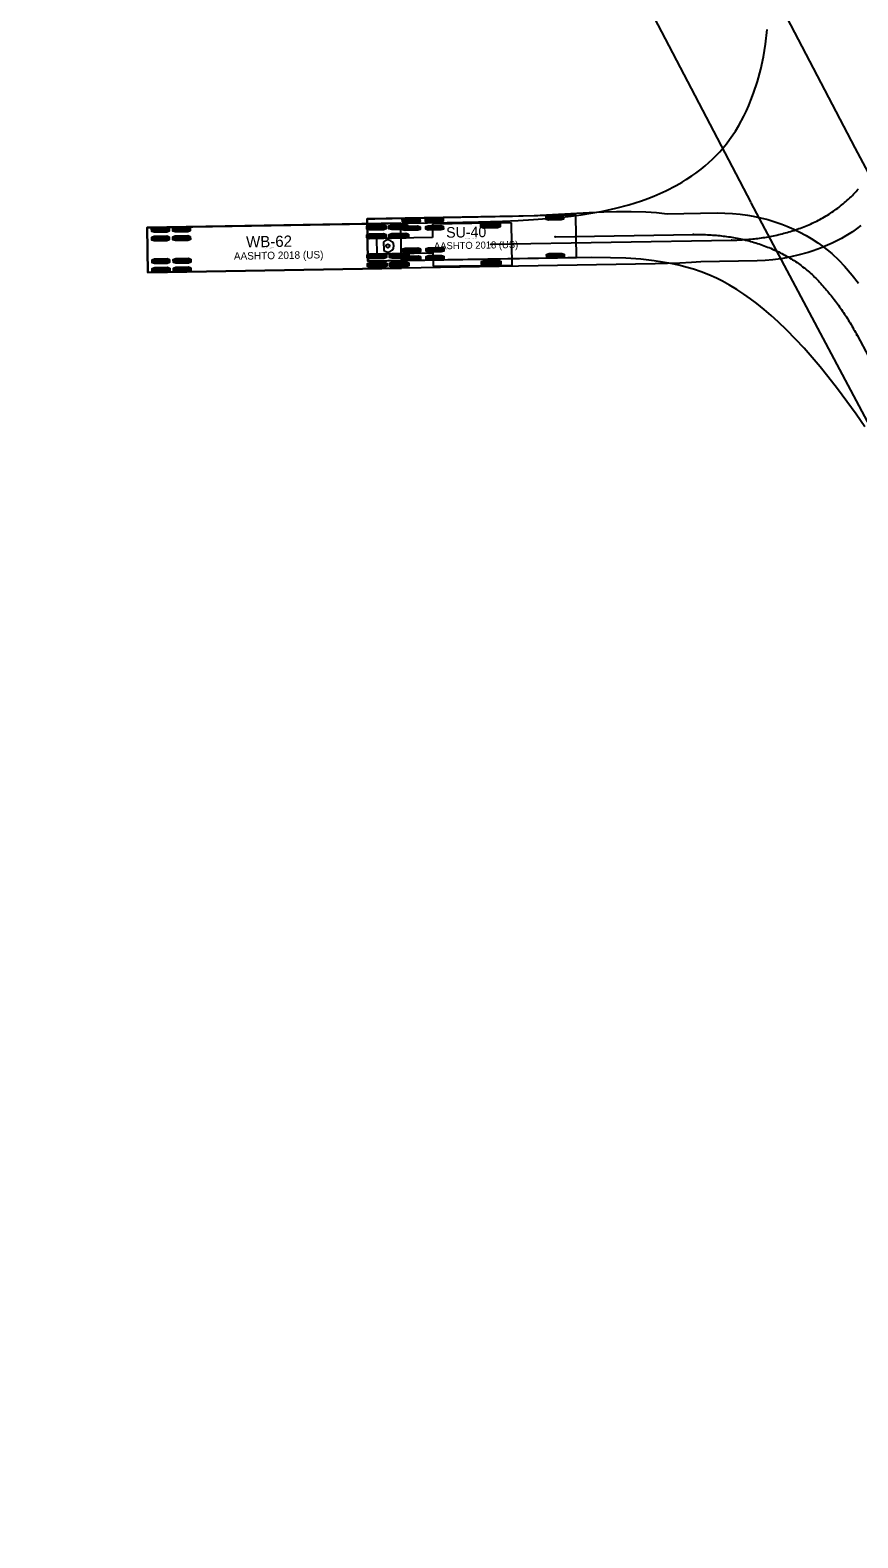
# Model space of a CAD drawing. Extents: x 2297881 to 2300600, y 559917 to 564426.
# Drawn here: x 2299240.6 to 2299397.2, y 561584.2 to 561869.7 of the extents above; entities that cross this region are included whole.
import ezdxf

# ---------------------------------------------------------------- set-up
doc = ezdxf.new("R2010")
doc.units = 0
for name, color, linetype in [('GE_X_Alignment', 7, 'Continuous'), ('PM_P_Lane_Line', 7, 'Continuous'), ('SC_Scratch1', 7, 'Continuous'), ('SN_X_Public', 7, 'Continuous')]:
    doc.layers.add(name, color=color, linetype=linetype)

msp = doc.modelspace()

# ---------------------------------------------------------------- linework, layer by layer
at = {"layer": 'GE_X_Alignment'}
for p, q in [((2298386.28, 563783.36), (2299396.64, 561847.4)), ((2299396.64, 561847.4), (2299991.21, 560726.85))]:
    msp.add_line(p, q, dxfattribs=at)
at = {"layer": 'PM_P_Lane_Line'}
for p, q in [((2298467.65, 563579.35), (2299376.95, 561837.04)), ((2299376.99, 561836.97), (2299547.48, 561515.65))]:
    msp.add_line(p, q, dxfattribs=at)
at = {"layer": 'SC_Scratch1'}
for p, q in [((2299310.69, 561833.1), (2299262.69, 561832.29)), ((2299262.69, 561832.29), (2299262.84, 561823.79)), ((2299266.85, 561832.13), (2299263.55, 561832.08)), ((2299270.85, 561832.2), (2299267.55, 561832.14)), ((2299270.85, 561831.97), (2299267.55, 561831.91)), ((2299307.93, 561832.57), (2299304.26, 561832.51)), ((2299307.93, 561832.34), (2299304.27, 561832.28)), ((2299307.94, 561832.11), (2299304.27, 561832.05)), ((2299312.13, 561832.64), (2299308.46, 561832.58)), ((2299312.13, 561832.41), (2299308.47, 561832.35)), ((2299312.14, 561832.18), (2299308.47, 561832.12)), ((2299310.83, 561824.6), (2299310.69, 561833.1)), ((2299310.69, 561833.1), (2299310.69, 561833.1)), ((2299331.69, 561833.2), (2299316.69, 561832.95)), ((2299316.69, 561832.95), (2299316.73, 561830.38)), ((2299329.53, 561832.93), (2299325.86, 561832.87)), ((2299329.53, 561832.7), (2299325.86, 561832.64)), ((2299329.53, 561832.47), (2299325.87, 561832.41)), ((2299331.82, 561825.2), (2299331.69, 561833.2)), ((2299331.69, 561833.2), (2299331.69, 561833.2)), ((2299266.85, 561831.9), (2299263.55, 561831.85)), ((2299266.86, 561831.67), (2299263.56, 561831.62)), ((2299266.88, 561830.48), (2299263.58, 561830.43)), ((2299266.88, 561830.25), (2299263.58, 561830.2)), ((2299266.88, 561830.02), (2299263.58, 561829.97)), ((2299270.86, 561831.74), (2299267.56, 561831.68)), ((2299270.87, 561830.55), (2299267.58, 561830.49)), ((2299270.88, 561830.32), (2299267.58, 561830.26)), ((2299270.88, 561830.09), (2299267.58, 561830.04)), ((2299307.96, 561830.92), (2299304.29, 561830.86)), ((2299307.96, 561830.69), (2299304.3, 561830.63)), ((2299307.96, 561830.46), (2299304.3, 561830.4)), ((2299316.73, 561830.38), (2299306.14, 561830.2)), ((2299306.14, 561830.2), (2299306.18, 561827.34)), ((2299307.44, 561829.6), (2299307.47, 561827.98)), ((2299312.16, 561830.99), (2299308.49, 561830.93)), ((2299312.16, 561830.76), (2299308.49, 561830.7)), ((2299312.16, 561830.53), (2299308.5, 561830.47)), ((2299327.76, 561829.13), (2299373.33, 561829.9)), ((2299266.95, 561826.2), (2299263.65, 561826.14)), ((2299270.95, 561826.27), (2299267.65, 561826.21)), ((2299308.02, 561827.14), (2299304.35, 561827.08)), ((2299308.02, 561826.91), (2299304.36, 561826.85)), ((2299308.03, 561826.68), (2299304.36, 561826.62)), ((2299306.18, 561827.34), (2299316.78, 561827.51)), ((2299312.22, 561827.21), (2299308.55, 561827.15)), ((2299312.22, 561826.98), (2299308.56, 561826.92)), ((2299312.23, 561826.75), (2299308.56, 561826.69)), ((2299316.78, 561827.51), (2299316.83, 561824.95)), ((2299262.84, 561823.79), (2299310.83, 561824.6)), ((2299266.95, 561825.97), (2299263.65, 561825.91)), ((2299266.96, 561825.74), (2299263.66, 561825.69)), ((2299266.98, 561824.55), (2299263.68, 561824.49)), ((2299266.98, 561824.32), (2299263.68, 561824.26)), ((2299266.98, 561824.09), (2299263.68, 561824.04)), ((2299270.95, 561826.04), (2299267.65, 561825.98)), ((2299270.95, 561825.81), (2299267.66, 561825.75)), ((2299270.97, 561824.62), (2299267.67, 561824.56)), ((2299270.98, 561824.39), (2299267.68, 561824.33)), ((2299270.98, 561824.16), (2299267.68, 561824.1)), ((2299308.05, 561825.49), (2299304.38, 561825.43)), ((2299308.05, 561825.26), (2299304.39, 561825.2)), ((2299308.06, 561825.03), (2299304.39, 561824.97)), ((2299312.25, 561825.56), (2299308.58, 561825.5)), ((2299312.25, 561825.33), (2299308.59, 561825.27)), ((2299312.26, 561825.1), (2299308.59, 561825.04)), ((2299316.83, 561824.95), (2299331.82, 561825.2)), ((2299329.65, 561825.85), (2299325.98, 561825.79)), ((2299329.65, 561825.62), (2299325.98, 561825.56)), ((2299329.65, 561825.39), (2299325.99, 561825.33))]:
    msp.add_line(p, q, dxfattribs=at)
for points in [[(2299263.99, 561832.31), (2299319.52, 561833.25), (2299325.4, 561833.37), (2299329.98, 561833.51), (2299332.91, 561833.63), (2299335.84, 561833.8), (2299338.43, 561833.99), (2299340.69, 561834.19), (2299342.93, 561834.45), (2299344.85, 561834.7), (2299347.06, 561835.06), (2299348.95, 561835.41), (2299351.43, 561835.97), (2299353.87, 561836.62), (2299356.27, 561837.38), (2299357.45, 561837.81), (2299358.62, 561838.26), (2299359.77, 561838.75), (2299360.91, 561839.27), (2299362.86, 561840.27), (2299363.94, 561840.89), (2299364.74, 561841.38), (2299365.79, 561842.06), (2299366.57, 561842.61), (2299367.57, 561843.37), (2299368.31, 561843.97), (2299369.73, 561845.26), (2299370.42, 561845.94), (2299371.08, 561846.65), (2299371.72, 561847.39), (2299372.35, 561848.16), (2299372.95, 561848.96), (2299373.58, 561849.86), (2299374.05, 561850.57), (2299374.69, 561851.63), (2299375.63, 561853.37), (2299376.13, 561854.39), (2299376.58, 561855.4), (2299376.99, 561856.4), (2299377.48, 561857.71), (2299378.21, 561859.93), (2299378.84, 561862.28), (2299379.35, 561864.64), (2299379.74, 561867.02), (2299380.08, 561869.82)], [(2299373.33, 561829.9), (2299373.66, 561829.9), (2299373.99, 561829.91), (2299374.33, 561829.93), (2299374.66, 561829.94), (2299374.99, 561829.96), (2299375.33, 561829.98), (2299375.66, 561830), (2299375.99, 561830.02), (2299376.32, 561830.05), (2299376.66, 561830.07), (2299376.99, 561830.1), (2299377.32, 561830.14), (2299377.65, 561830.17), (2299377.98, 561830.21), (2299378.31, 561830.25), (2299378.64, 561830.3), (2299378.97, 561830.34), (2299379.3, 561830.39), (2299379.63, 561830.44), (2299379.96, 561830.5), (2299380.29, 561830.55), (2299380.62, 561830.61), (2299380.95, 561830.68), (2299381.27, 561830.74), (2299381.6, 561830.81), (2299381.92, 561830.88), (2299382.25, 561830.95), (2299382.57, 561831.03), (2299382.9, 561831.11), (2299383.22, 561831.2), (2299383.54, 561831.28), (2299383.86, 561831.37), (2299384.18, 561831.46), (2299384.5, 561831.56), (2299384.82, 561831.66), (2299385.14, 561831.76), (2299385.45, 561831.87), (2299385.77, 561831.97), (2299386.08, 561832.09), (2299386.4, 561832.2), (2299386.71, 561832.32), (2299387.02, 561832.44), (2299387.33, 561832.57), (2299387.64, 561832.69), (2299387.94, 561832.83), (2299388.25, 561832.96), (2299388.55, 561833.1), (2299388.85, 561833.24), (2299389.15, 561833.39), (2299389.45, 561833.53), (2299389.75, 561833.69), (2299390.04, 561833.84), (2299390.33, 561834), (2299390.62, 561834.16), (2299390.91, 561834.33), (2299391.2, 561834.5), (2299391.49, 561834.67), (2299391.77, 561834.85), (2299392.05, 561835.03), (2299392.33, 561835.21), (2299392.6, 561835.4), (2299392.88, 561835.59), (2299393.15, 561835.78), (2299393.42, 561835.98), (2299393.68, 561836.18), (2299393.95, 561836.39), (2299394.21, 561836.59), (2299394.47, 561836.8), (2299394.72, 561837.02), (2299394.97, 561837.24), (2299395.22, 561837.46), (2299395.47, 561837.68), (2299395.71, 561837.91), (2299395.95, 561838.14), (2299396.19, 561838.38), (2299396.42, 561838.62), (2299396.65, 561838.86), (2299396.88, 561839.1), (2299397.1, 561839.35), (2299397.32, 561839.6)], [(2299397.78, 561832.66), (2299396.99, 561832.08), (2299396.19, 561831.51), (2299394.95, 561830.73), (2299394.1, 561830.24), (2299392.36, 561829.34), (2299391.48, 561828.93), (2299390.13, 561828.37), (2299388.76, 561827.87), (2299387.83, 561827.58), (2299385.86, 561827.04), (2299384.8, 561826.79), (2299383.73, 561826.58), (2299382.64, 561826.4), (2299381.16, 561826.21), (2299379.66, 561826.07), (2299378.14, 561825.99), (2299367.51, 561825.8), (2299365.71, 561825.67), (2299363.54, 561825.55), (2299358.85, 561825.41), (2299262.84, 561823.79), (2299262.69, 561832.29), (2299263.99, 561832.31)]]:
    msp.add_lwpolyline(points, dxfattribs=at)
for points in [[(2299266.85, 561832.19), (2299266.86, 561831.62), (2299266.4, 561831.44), (2299264.02, 561831.4), (2299263.56, 561831.56), (2299263.55, 561832.13), (2299264.01, 561832.31), (2299266.38, 561832.35)], [(2299270.85, 561832.26), (2299270.86, 561831.68), (2299270.4, 561831.5), (2299268.02, 561831.46), (2299267.56, 561831.63), (2299267.55, 561832.2), (2299268.01, 561832.38), (2299270.38, 561832.42)], [(2299307.93, 561832.63), (2299307.94, 561832.06), (2299307.43, 561831.87), (2299304.79, 561831.83), (2299304.27, 561831.99), (2299304.26, 561832.57), (2299304.77, 561832.75), (2299307.41, 561832.79)], [(2299312.13, 561832.7), (2299312.14, 561832.13), (2299311.63, 561831.94), (2299308.99, 561831.9), (2299308.47, 561832.06), (2299308.46, 561832.64), (2299308.97, 561832.82), (2299311.61, 561832.86)], [(2299329.53, 561832.99), (2299329.54, 561832.42), (2299329.02, 561832.24), (2299326.39, 561832.19), (2299325.87, 561832.36), (2299325.86, 561832.93), (2299326.37, 561833.11), (2299329.01, 561833.15)], [(2299266.87, 561830.54), (2299266.88, 561829.97), (2299266.43, 561829.79), (2299264.05, 561829.75), (2299263.58, 561829.91), (2299263.58, 561830.48), (2299264.03, 561830.66), (2299266.41, 561830.7)], [(2299270.87, 561830.61), (2299270.88, 561830.03), (2299270.42, 561829.85), (2299268.05, 561829.81), (2299267.58, 561829.98), (2299267.57, 561830.55), (2299268.03, 561830.73), (2299270.41, 561830.77)], [(2299307.96, 561830.98), (2299307.97, 561830.41), (2299307.46, 561830.22), (2299304.82, 561830.18), (2299304.3, 561830.34), (2299304.29, 561830.92), (2299304.8, 561831.1), (2299307.44, 561831.14)], [(2299312.16, 561831.05), (2299312.17, 561830.48), (2299311.65, 561830.3), (2299309.02, 561830.25), (2299308.5, 561830.41), (2299308.49, 561830.99), (2299309, 561831.17), (2299311.64, 561831.21)], [(2299266.95, 561826.26), (2299266.96, 561825.68), (2299266.5, 561825.5), (2299264.12, 561825.46), (2299263.66, 561825.63), (2299263.65, 561826.2), (2299264.11, 561826.38), (2299266.48, 561826.42)], [(2299270.95, 561826.32), (2299270.96, 561825.75), (2299270.5, 561825.57), (2299268.12, 561825.53), (2299267.66, 561825.7), (2299267.65, 561826.27), (2299268.11, 561826.45), (2299270.48, 561826.49)], [(2299308.02, 561827.19), (2299308.03, 561826.62), (2299307.52, 561826.44), (2299304.88, 561826.4), (2299304.36, 561826.56), (2299304.35, 561827.13), (2299304.86, 561827.31), (2299307.5, 561827.36)], [(2299312.22, 561827.27), (2299312.23, 561826.69), (2299311.72, 561826.51), (2299309.08, 561826.47), (2299308.56, 561826.63), (2299308.55, 561827.2), (2299309.06, 561827.38), (2299311.7, 561827.43)], [(2299266.97, 561824.61), (2299266.98, 561824.03), (2299266.52, 561823.85), (2299264.15, 561823.81), (2299263.68, 561823.98), (2299263.67, 561824.55), (2299264.13, 561824.73), (2299266.51, 561824.77)], [(2299270.97, 561824.67), (2299270.98, 561824.1), (2299270.52, 561823.92), (2299268.15, 561823.88), (2299267.68, 561824.05), (2299267.67, 561824.62), (2299268.13, 561824.8), (2299270.51, 561824.84)], [(2299308.05, 561825.55), (2299308.06, 561824.97), (2299307.55, 561824.79), (2299304.91, 561824.75), (2299304.39, 561824.91), (2299304.38, 561825.48), (2299304.89, 561825.66), (2299307.53, 561825.71)], [(2299312.25, 561825.62), (2299312.26, 561825.04), (2299311.75, 561824.86), (2299309.11, 561824.82), (2299308.59, 561824.98), (2299308.58, 561825.55), (2299309.09, 561825.73), (2299311.73, 561825.78)], [(2299329.64, 561825.91), (2299329.65, 561825.34), (2299329.14, 561825.15), (2299326.5, 561825.11), (2299325.99, 561825.27), (2299325.98, 561825.85), (2299326.49, 561826.03), (2299329.13, 561826.07)]]:
    msp.add_lwpolyline(points, close=True, dxfattribs=at)
for centre, radius in [((2299308.26, 561828.8), 0.34), ((2299327.76, 561829.13), 0.0417), ((2299373.33, 561829.9), 0.0417), ((2299373.33, 561829.9), 0.0417)]:
    msp.add_circle(centre, radius, dxfattribs=at)
msp.add_arc((2299308.26, 561828.8), 1.14, 225.9612, 135.9612, dxfattribs=at)
at = {"layer": 'SN_X_Public'}
for p, q in [((2299343.86, 561834.61), (2299304.37, 561833.95)), ((2299304.37, 561833.95), (2299304.5, 561825.95)), ((2299314.34, 561833.91), (2299311.01, 561833.85)), ((2299314.34, 561833.7), (2299311.01, 561833.64)), ((2299314.35, 561833.49), (2299311.01, 561833.43)), ((2299314.36, 561832.41), (2299311.03, 561832.35)), ((2299314.37, 561832.2), (2299311.03, 561832.14)), ((2299314.37, 561831.99), (2299311.04, 561831.93)), ((2299318.74, 561833.98), (2299315.4, 561833.92)), ((2299318.74, 561833.77), (2299315.41, 561833.72)), ((2299318.74, 561833.56), (2299315.41, 561833.51)), ((2299318.76, 561832.48), (2299315.43, 561832.42)), ((2299318.77, 561832.27), (2299315.43, 561832.22)), ((2299318.77, 561832.06), (2299315.44, 561832.01)), ((2299341.53, 561834.36), (2299338.2, 561834.31)), ((2299341.54, 561834.15), (2299338.21, 561834.1)), ((2299341.54, 561833.95), (2299338.21, 561833.89)), ((2299344, 561826.61), (2299343.86, 561834.61)), ((2299343.86, 561834.61), (2299343.86, 561834.61)), ((2299339.93, 561830.54), (2299366.07, 561830.98)), ((2299304.5, 561825.95), (2299344, 561826.61)), ((2299314.43, 561828.24), (2299311.1, 561828.18)), ((2299314.44, 561828.03), (2299311.1, 561827.98)), ((2299314.44, 561827.82), (2299311.11, 561827.77)), ((2299314.46, 561826.74), (2299311.13, 561826.69)), ((2299314.46, 561826.53), (2299311.13, 561826.48)), ((2299314.47, 561826.32), (2299311.13, 561826.27)), ((2299318.83, 561828.31), (2299315.5, 561828.26)), ((2299318.84, 561828.11), (2299315.5, 561828.05)), ((2299318.84, 561827.9), (2299315.51, 561827.84)), ((2299318.86, 561826.81), (2299315.53, 561826.76)), ((2299318.86, 561826.61), (2299315.53, 561826.55)), ((2299318.86, 561826.4), (2299315.53, 561826.34)), ((2299341.65, 561827.2), (2299338.32, 561827.14)), ((2299341.66, 561826.99), (2299338.33, 561826.93)), ((2299341.66, 561826.78), (2299338.33, 561826.72)), ((2299397.07, 561811.91), (2299461.04, 561691.4))]:
    msp.add_line(p, q, dxfattribs=at)
for points in [[(2299305.81, 561833.97), (2299331.86, 561834.42), (2299335.98, 561834.59), (2299346.37, 561835.17), (2299349.14, 561835.28), (2299351.56, 561835.34), (2299354.33, 561835.34), (2299357.08, 561835.27), (2299359.12, 561835.13), (2299361.14, 561834.9), (2299370.57, 561835.05), (2299372.04, 561835.02), (2299373.49, 561834.94), (2299374.93, 561834.8), (2299376.36, 561834.61), (2299377.41, 561834.43), (2299378.8, 561834.14), (2299380.17, 561833.79), (2299381.52, 561833.39), (2299382.84, 561832.94), (2299383.81, 561832.56), (2299385.11, 561832), (2299386.12, 561831.51), (2299387.43, 561830.81), (2299388.39, 561830.24), (2299389.64, 561829.43), (2299390.54, 561828.78), (2299391.43, 561828.09), (2299392.29, 561827.37), (2299393.65, 561826.09), (2299394.69, 561824.99), (2299396.16, 561823.27), (2299397.32, 561821.78)], [(2299398.57, 561794.54), (2299396.91, 561796.93), (2299395.17, 561799.36), (2299393.39, 561801.74), (2299391.57, 561804.08), (2299390.09, 561805.9), (2299388.58, 561807.7), (2299387.04, 561809.45), (2299385.45, 561811.17), (2299383.81, 561812.84), (2299382.13, 561814.46), (2299380.82, 561815.64), (2299379.49, 561816.79), (2299378.11, 561817.9), (2299376.91, 561818.81), (2299375.63, 561819.71), (2299374.31, 561820.57), (2299372.96, 561821.38), (2299371.59, 561822.12), (2299370.46, 561822.68), (2299369.03, 561823.31), (2299367.57, 561823.88), (2299366.09, 561824.4), (2299364.89, 561824.76), (2299363.36, 561825.15), (2299361.82, 561825.49), (2299360.26, 561825.77), (2299358.69, 561826), (2299356.15, 561826.29), (2299353.28, 561826.49), (2299350.38, 561826.59), (2299346.83, 561826.63), (2299342.31, 561826.58), (2299304.5, 561825.95), (2299304.37, 561833.95), (2299305.81, 561833.97)], [(2299366.07, 561830.98), (2299366.41, 561830.99), (2299366.74, 561830.99), (2299367.07, 561830.99), (2299367.41, 561830.98), (2299367.74, 561830.97), (2299368.07, 561830.97), (2299368.41, 561830.95), (2299368.74, 561830.94), (2299369.07, 561830.92), (2299369.4, 561830.9), (2299369.74, 561830.88), (2299370.07, 561830.86), (2299370.4, 561830.83), (2299370.73, 561830.8), (2299371.07, 561830.77), (2299371.4, 561830.73), (2299371.73, 561830.69), (2299372.06, 561830.65), (2299372.39, 561830.61), (2299372.72, 561830.56), (2299373.05, 561830.51), (2299373.38, 561830.46), (2299373.71, 561830.4), (2299374.03, 561830.34), (2299374.36, 561830.28), (2299374.69, 561830.21), (2299375.02, 561830.14), (2299375.34, 561830.07), (2299375.67, 561830), (2299375.99, 561829.92), (2299376.31, 561829.84), (2299376.64, 561829.76), (2299376.96, 561829.67), (2299377.28, 561829.58), (2299377.6, 561829.48), (2299377.92, 561829.39), (2299378.23, 561829.29), (2299378.55, 561829.18), (2299378.87, 561829.07), (2299379.18, 561828.96), (2299379.49, 561828.85), (2299379.81, 561828.73), (2299380.12, 561828.61), (2299380.43, 561828.49), (2299380.73, 561828.36), (2299381.04, 561828.23), (2299381.35, 561828.09), (2299381.65, 561827.96), (2299381.95, 561827.82), (2299382.25, 561827.67), (2299382.55, 561827.52), (2299382.85, 561827.37), (2299383.14, 561827.21), (2299383.43, 561827.06), (2299383.73, 561826.89), (2299384.02, 561826.73), (2299384.3, 561826.56), (2299384.59, 561826.39), (2299384.87, 561826.21), (2299385.15, 561826.03), (2299385.43, 561825.85), (2299385.71, 561825.66), (2299385.98, 561825.47), (2299386.25, 561825.27), (2299386.52, 561825.08), (2299386.78, 561824.88), (2299387.05, 561824.67), (2299387.31, 561824.47), (2299387.57, 561824.25), (2299387.82, 561824.04), (2299388.07, 561823.82), (2299388.32, 561823.6), (2299388.57, 561823.38), (2299388.81, 561823.15), (2299389.05, 561822.92), (2299389.29, 561822.68), (2299389.52, 561822.44), (2299389.75, 561822.2), (2299389.98, 561821.96), (2299390.21, 561821.71), (2299390.43, 561821.47), (2299390.65, 561821.22), (2299390.87, 561820.97), (2299391.09, 561820.71), (2299391.3, 561820.46), (2299391.52, 561820.2), (2299391.73, 561819.95), (2299391.94, 561819.69), (2299392.15, 561819.43), (2299392.36, 561819.17), (2299392.56, 561818.91), (2299392.77, 561818.64), (2299392.97, 561818.38), (2299393.17, 561818.11), (2299393.36, 561817.84), (2299393.56, 561817.57), (2299393.75, 561817.3), (2299393.95, 561817.03), (2299394.14, 561816.75), (2299394.33, 561816.48), (2299394.51, 561816.2), (2299394.7, 561815.92), (2299394.88, 561815.65), (2299395.06, 561815.36), (2299395.24, 561815.08), (2299395.41, 561814.8), (2299395.59, 561814.52), (2299395.76, 561814.23), (2299395.93, 561813.94), (2299396.1, 561813.66), (2299396.26, 561813.37), (2299396.43, 561813.08), (2299396.59, 561812.79), (2299396.75, 561812.49), (2299396.91, 561812.2), (2299397.07, 561811.91)]]:
    msp.add_lwpolyline(points, dxfattribs=at)
for points in [[(2299314.34, 561833.96), (2299314.35, 561833.44), (2299313.88, 561833.27), (2299311.48, 561833.23), (2299311.01, 561833.38), (2299311, 561833.9), (2299311.47, 561834.07), (2299313.87, 561834.11)], [(2299314.36, 561832.46), (2299314.37, 561831.94), (2299313.91, 561831.77), (2299311.51, 561831.73), (2299311.04, 561831.88), (2299311.03, 561832.4), (2299311.49, 561832.57), (2299313.89, 561832.61)], [(2299318.74, 561834.03), (2299318.75, 561833.51), (2299318.28, 561833.35), (2299315.88, 561833.31), (2299315.41, 561833.46), (2299315.4, 561833.98), (2299315.87, 561834.14), (2299318.27, 561834.18)], [(2299318.76, 561832.53), (2299318.77, 561832.01), (2299318.31, 561831.85), (2299315.91, 561831.81), (2299315.44, 561831.96), (2299315.43, 561832.48), (2299315.89, 561832.64), (2299318.29, 561832.68)], [(2299341.53, 561834.41), (2299341.54, 561833.89), (2299341.08, 561833.73), (2299338.68, 561833.69), (2299338.21, 561833.84), (2299338.2, 561834.36), (2299338.66, 561834.52), (2299341.06, 561834.56)], [(2299314.43, 561828.29), (2299314.44, 561827.77), (2299313.98, 561827.61), (2299311.58, 561827.57), (2299311.11, 561827.72), (2299311.1, 561828.24), (2299311.56, 561828.4), (2299313.96, 561828.44)], [(2299314.46, 561826.79), (2299314.47, 561826.27), (2299314, 561826.11), (2299311.6, 561826.07), (2299311.13, 561826.22), (2299311.12, 561826.74), (2299311.59, 561826.9), (2299313.99, 561826.94)], [(2299318.83, 561828.37), (2299318.84, 561827.85), (2299318.38, 561827.68), (2299315.98, 561827.64), (2299315.51, 561827.79), (2299315.5, 561828.31), (2299315.96, 561828.47), (2299318.36, 561828.52)], [(2299318.86, 561826.87), (2299318.87, 561826.35), (2299318.4, 561826.18), (2299316, 561826.14), (2299315.53, 561826.29), (2299315.52, 561826.81), (2299315.99, 561826.98), (2299318.39, 561827.02)], [(2299341.65, 561827.25), (2299341.66, 561826.73), (2299341.2, 561826.56), (2299338.8, 561826.52), (2299338.33, 561826.67), (2299338.32, 561827.19), (2299338.78, 561827.36), (2299341.18, 561827.4)]]:
    msp.add_lwpolyline(points, close=True, dxfattribs=at)
for centre in [(2299339.93, 561830.54), (2299366.07, 561830.98), (2299366.07, 561830.98), (2299397.07, 561811.91)]:
    msp.add_circle(centre, 0.0417, dxfattribs=at)

# ---------------------------------------------------------------- texts
at = {"layer": 'SC_Scratch1'}
for s, height, p in [('WB-62', 2.125, (2299281.45, 561828.52)), ('AASHTO 2018 (US)', 1.4167, (2299279.13, 561826.18)), ('(c) 2021 Transoft Solutions, Inc. All rights reserved.', 0.085, (2299285.03, 561828.37))]:
    msp.add_text(s, height=height, rotation=0.9612, dxfattribs=at).set_placement(p)
at = {"layer": 'SN_X_Public'}
for s, height, p in [('SU-40', 2, (2299319.32, 561830.36)), ('AASHTO 2018 (US)', 1.3333, (2299317, 561828.15)), ('(c) 2021 Transoft Solutions, Inc. All rights reserved.', 0.08, (2299322.55, 561830.21))]:
    msp.add_text(s, height=height, rotation=0.9612, dxfattribs=at).set_placement(p)

doc.saveas('drawing.dxf')
